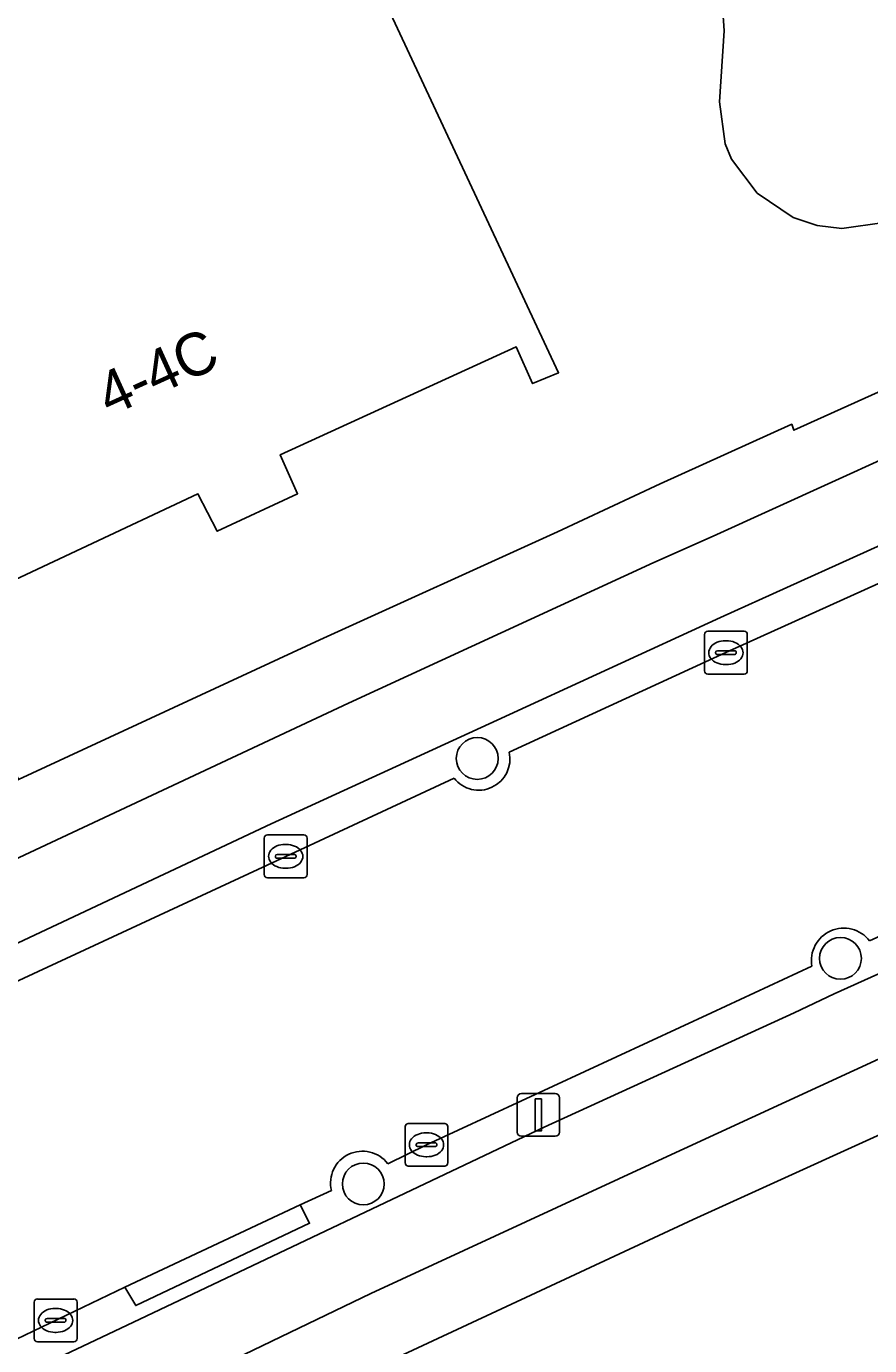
# Model space of a CAD drawing. Extents: x 157320 to 158835, y 386650 to 388491.
# Drawn here: x 157785.79 to 157805.51, y 387742.21 to 387773.08 of the extents above; entities that cross this region are included whole.
import ezdxf

# ---------------------------------------------------------------- set-up
doc = ezdxf.new("R2010")
doc.units = 0
for name, color, linetype in [('IMGEO_Berm_open', 7, 'Continuous'), ('IMGEO_Boom', 7, 'Continuous'), ('IMGEO_Erf', 7, 'Continuous'), ('IMGEO_Fietspad_open', 7, 'Continuous'), ('IMGEO_Kolk', 7, 'Continuous'), ('IMGEO_Lichtmast', 7, 'Continuous'), ('IMGEO_Pand', 7, 'Continuous'), ('IMGEO_Pand_nummerreeks', 7, 'Continuous'), ('IMGEO_Rijbaan_lokaal_open', 7, 'Continuous'), ('IMGEO_Voetpad_open', 7, 'Continuous')]:
    doc.layers.add(name, color=color, linetype=linetype)

msp = doc.modelspace()

# ---------------------------------------------------------------- linework, layer by layer
at = {"layer": 'IMGEO_Berm_open'}
for points in [[(157830.412, 387771.96), (157824.626, 387769.413), (157818.792, 387766.794), (157811.326, 387763.457), (157802.02, 387759.247), (157796.796, 387756.844), (157791.514, 387754.422), (157784.002, 387750.892), (157782.111, 387750), (157777.727, 387747.932), (157769.083, 387743.789), (157769.287, 387743.353), (157770.466, 387743.543), (157770.712, 387743.64), (157771.088, 387743.794)], [(157797.08, 387756.095), (157802.146, 387758.426), (157809.439, 387761.726)], [(157774.522, 387737.042), (157774.329, 387736.951), (157770.945, 387735.285), (157769.959, 387734.638), (157770.171, 387734.176), (157788.445, 387742.834), (157797.893, 387747.327), (157803.739, 387750), (157804.677, 387750.444), (157810.091, 387752.884), (157815.175, 387755.151), (157823.216, 387758.725)], [(157821.265, 387758.745), (157814.813, 387755.887), (157809.798, 387753.659), (157809.994, 387753.177), (157806.556, 387751.612), (157806.359, 387752.075), (157805.505, 387751.685)], [(157783.626, 387749.838), (157783.975, 387750), (157791.855, 387753.66), (157795.79, 387755.49)], [(157804.156, 387751.089), (157801.806, 387750), (157795.145, 387746.914), (157794.24, 387746.471)], [(157792.922, 387745.842), (157792.191, 387745.512), (157792.414, 387745.076), (157788.35, 387743.151), (157788.095, 387743.586), (157782.436, 387740.872), (157778.846, 387739.129)]]:
    msp.add_lwpolyline(points, dxfattribs=at)
msp.add_lwpolyline([(157792.414, 387745.076), (157792.191, 387745.512), (157788.095, 387743.586), (157788.35, 387743.151)], close=True, dxfattribs=at)
for centre, radius, start, end in [((157796.367, 387755.938), 0.73, 217.851, 12.4014), ((157804.903, 387751.223), 0.759, 37.5048, 190.1677), ((157793.648, 387746.016), 0.747, 37.5525, 193.472)]:
    msp.add_arc(centre, radius, start, end, dxfattribs=at)
at = {"layer": 'IMGEO_Boom'}
for centre in [(157796.332, 387755.951), (157804.824, 387751.274), (157793.668, 387745.996)]:
    msp.add_circle(centre, 0.489, dxfattribs=at)
at = {"layer": 'IMGEO_Erf'}
for points in [[(157805.842, 387768.492), (157804.852, 387768.352), (157804.279, 387768.423), (157803.719, 387768.609), (157802.878, 387769.172), (157802.279, 387769.973), (157802.125, 387770.327), (157801.998, 387771.315), (157802.102, 387772.972), (157802.021, 387774.247), (157801.408, 387776.7), (157801.444, 387777.329), (157801.556, 387777.747), (157801.982, 387778.5), (157802.775, 387779.152), (157803.626, 387777.358), (157804.993, 387778.006), (157802.456, 387783.356), (157816.749, 387790.135)], [(157773.659, 387781.323), (157777.46, 387772.709), (157791.548, 387779.289), (157798.235, 387764.975), (157797.627, 387764.722), (157797.242, 387765.581), (157791.728, 387763.055), (157792.131, 387762.142), (157790.254, 387761.268), (157789.801, 387762.139), (157784.354, 387759.587), (157784.75, 387758.69), (157784.186, 387758.429), (157785.609, 387755.46), (157792.651, 387758.723), (157798.206, 387761.256), (157800.606, 387762.378), (157803.685, 387763.769), (157803.737, 387763.63), (157814.47, 387768.474)], [(157864.126, 387772.947), (157837.386, 387761.239), (157831.138, 387758.491), (157825.817, 387756.137), (157813.3, 387750.568), (157812.042, 387750), (157807.394, 387747.901), (157801.377, 387745.165), (157794.254, 387741.847)]]:
    msp.add_lwpolyline(points, dxfattribs=at)
at = {"layer": 'IMGEO_Fietspad_open'}
for points in [[(157864.008, 387776.443), (157863.068, 387776.049), (157863.031, 387776.185), (157843.156, 387767.523), (157835.06, 387763.984), (157823.216, 387758.725), (157815.175, 387755.151), (157810.091, 387752.884), (157804.677, 387750.444), (157803.739, 387750), (157797.893, 387747.327), (157788.445, 387742.834), (157770.171, 387734.176), (157769.959, 387734.638)], [(157767.728, 387731.043), (157779.548, 387736.625), (157789.197, 387741.196), (157793.841, 387743.435), (157800.368, 387746.45), (157806.723, 387749.381), (157808.098, 387750), (157812.222, 387751.857), (157817.687, 387754.31), (157825.13, 387757.594), (157830.503, 387759.975), (157836.688, 387762.719), (157865.106, 387775.129)], [(157829.725, 387773.675), (157827.906, 387772.832), (157822.414, 387770.394), (157817.284, 387768.125), (157813.4, 387766.376), (157808.696, 387764.269), (157801.848, 387761.151), (157800.462, 387760.535), (157793.32, 387757.246), (157777.795, 387749.967), (157770.699, 387746.575), (157765.921, 387744.31)], [(157769.287, 387743.353), (157769.083, 387743.789), (157777.727, 387747.932), (157782.111, 387750), (157784.002, 387750.892), (157791.514, 387754.422), (157796.796, 387756.844), (157802.02, 387759.247), (157811.326, 387763.457), (157818.792, 387766.794), (157824.626, 387769.413), (157830.412, 387771.96)]]:
    msp.add_lwpolyline(points, dxfattribs=at)
at = {"layer": 'IMGEO_Kolk'}
for p, q in [((157801.645, 387758), (157801.645, 387758.852)), ((157801.72, 387758.926), (157802.572, 387758.926)), ((157802.646, 387758.852), (157802.646, 387758)), ((157802.133, 387758.706), (157802.158, 387758.706)), ((157801.904, 387758.42), (157801.904, 387758.432)), ((157802.342, 387758.383), (157801.944, 387758.383)), ((157801.947, 387758.469), (157802.345, 387758.469)), ((157802.388, 387758.432), (157802.388, 387758.42)), ((157802.572, 387757.926), (157801.72, 387757.926)), ((157802.156, 387758.146), (157802.131, 387758.146)), ((157791.428, 387754.161), (157792.28, 387754.161)), ((157791.353, 387753.235), (157791.353, 387754.087)), ((157791.841, 387753.941), (157791.866, 387753.941)), ((157792.354, 387754.087), (157792.354, 387753.235)), ((157791.612, 387753.655), (157791.612, 387753.667)), ((157792.05, 387753.618), (157791.652, 387753.618)), ((157791.655, 387753.704), (157792.053, 387753.704)), ((157792.096, 387753.667), (157792.096, 387753.655)), ((157791.864, 387753.381), (157791.839, 387753.381)), ((157792.28, 387753.161), (157791.428, 387753.161)), ((157794.72, 387747.413), (157795.572, 387747.413)), ((157794.645, 387746.487), (157794.645, 387747.339)), ((157795.133, 387747.193), (157795.158, 387747.193)), ((157795.646, 387747.339), (157795.646, 387746.487)), ((157794.904, 387746.907), (157794.904, 387746.919)), ((157795.342, 387746.87), (157794.944, 387746.87)), ((157794.947, 387746.956), (157795.345, 387746.956)), ((157795.388, 387746.919), (157795.388, 387746.907)), ((157795.156, 387746.633), (157795.131, 387746.633)), ((157795.572, 387746.413), (157794.72, 387746.413)), ((157785.974, 387742.379), (157785.974, 387743.231)), ((157786.049, 387743.305), (157786.901, 387743.305)), ((157786.462, 387743.085), (157786.487, 387743.085)), ((157786.975, 387743.231), (157786.975, 387742.379)), ((157786.233, 387742.799), (157786.233, 387742.811)), ((157786.671, 387742.762), (157786.273, 387742.762)), ((157786.276, 387742.848), (157786.674, 387742.848)), ((157786.717, 387742.811), (157786.717, 387742.799)), ((157786.485, 387742.525), (157786.46, 387742.525)), ((157786.901, 387742.305), (157786.049, 387742.305))]:
    msp.add_line(p, q, dxfattribs=at)
for points in [[(157801.645, 387758), (157801.645, 387758.852)], [(157801.72, 387758.926), (157802.572, 387758.926)], [(157802.646, 387758.852), (157802.646, 387758)], [(157802.572, 387757.926), (157801.72, 387757.926)], [(157791.428, 387754.161), (157792.28, 387754.161)], [(157791.353, 387753.235), (157791.353, 387754.087)], [(157792.354, 387754.087), (157792.354, 387753.235)], [(157792.28, 387753.161), (157791.428, 387753.161)], [(157794.72, 387747.413), (157795.572, 387747.413)], [(157794.645, 387746.487), (157794.645, 387747.339)], [(157795.646, 387747.339), (157795.646, 387746.487)], [(157795.572, 387746.413), (157794.72, 387746.413)], [(157785.974, 387742.379), (157785.974, 387743.231)], [(157786.049, 387743.305), (157786.901, 387743.305)], [(157786.975, 387743.231), (157786.975, 387742.379)], [(157786.901, 387742.305), (157786.049, 387742.305)]]:
    msp.add_lwpolyline(points, dxfattribs=at)
for centre, radius, start, end in [((157801.722, 387758.85), 0.0765, 91.552, 178.448), ((157801.722, 387758.85), 0.0765, 91.552, 178.448), ((157802.57, 387758.85), 0.0765, 1.552, 88.448), ((157802.57, 387758.85), 0.0765, 1.552, 88.448), ((157801.944, 387758.429), 0.0403, 85.8775, 175.7526), ((157801.941, 387758.419), 0.0366, 178.938, 274.7102), ((157802.345, 387758.426), 0.043, 264.8664, 352.4533), ((157802.349, 387758.431), 0.0386, 1.7309, 96.639), ((157801.722, 387758.002), 0.0765, 181.552, 268.448), ((157801.722, 387758.002), 0.0765, 181.552, 268.448), ((157802.57, 387758.002), 0.0765, 271.552, 358.448), ((157802.57, 387758.002), 0.0765, 271.552, 358.448), ((157791.43, 387754.085), 0.0765, 91.552, 178.448), ((157791.43, 387754.085), 0.0765, 91.552, 178.448), ((157792.278, 387754.085), 0.0765, 1.552, 88.448), ((157792.278, 387754.085), 0.0765, 1.552, 88.448), ((157791.652, 387753.664), 0.0403, 85.8775, 175.7526), ((157791.649, 387753.654), 0.0366, 178.938, 274.7102), ((157792.053, 387753.661), 0.043, 264.8664, 352.4533), ((157792.057, 387753.666), 0.0386, 1.7309, 96.639), ((157791.43, 387753.237), 0.0765, 181.552, 268.448), ((157791.43, 387753.237), 0.0765, 181.552, 268.448), ((157792.278, 387753.237), 0.0765, 271.552, 358.448), ((157792.278, 387753.237), 0.0765, 271.552, 358.448), ((157794.722, 387747.337), 0.0765, 91.552, 178.448), ((157794.722, 387747.337), 0.0765, 91.552, 178.448), ((157795.57, 387747.337), 0.0765, 1.552, 88.448), ((157795.57, 387747.337), 0.0765, 1.552, 88.448), ((157794.944, 387746.916), 0.0403, 85.8775, 175.7526), ((157794.941, 387746.906), 0.0366, 178.938, 274.7102), ((157795.345, 387746.913), 0.043, 264.8664, 352.4533), ((157795.349, 387746.918), 0.0386, 1.7309, 96.639), ((157794.722, 387746.489), 0.0765, 181.552, 268.448), ((157794.722, 387746.489), 0.0765, 181.552, 268.448), ((157795.57, 387746.489), 0.0765, 271.552, 358.448), ((157795.57, 387746.489), 0.0765, 271.552, 358.448), ((157786.051, 387743.229), 0.0765, 91.552, 178.448), ((157786.051, 387743.229), 0.0765, 91.552, 178.448), ((157786.899, 387743.229), 0.0765, 1.552, 88.448), ((157786.899, 387743.229), 0.0765, 1.552, 88.448), ((157786.273, 387742.808), 0.0403, 85.8775, 175.7526), ((157786.27, 387742.798), 0.0366, 178.938, 274.7102), ((157786.674, 387742.805), 0.043, 264.8664, 352.4533), ((157786.678, 387742.81), 0.0386, 1.7309, 96.639), ((157786.051, 387742.381), 0.0765, 181.552, 268.448), ((157786.051, 387742.381), 0.0765, 181.552, 268.448), ((157786.899, 387742.381), 0.0765, 271.552, 358.448), ((157786.899, 387742.381), 0.0765, 271.552, 358.448)]:
    msp.add_arc(centre, radius, start, end, dxfattribs=at)
for centre, major_axis, ratio, start_param, end_param in [((157802.132, 387758.426), (-0.387, 0.002), 0.722429, 4.712389, 7.853982), ((157802.157, 387758.426), (-0.39, 0.002), 0.717154, 1.570796, 4.712389), ((157791.84, 387753.661), (-0.387, 0.002), 0.722429, 4.712389, 7.853982), ((157791.865, 387753.661), (-0.39, 0.002), 0.717154, 1.570796, 4.712389), ((157795.132, 387746.913), (-0.387, 0.002), 0.722429, 4.712389, 7.853982), ((157795.157, 387746.913), (-0.39, 0.002), 0.717154, 1.570796, 4.712389), ((157786.461, 387742.805), (-0.387, 0.002), 0.722429, 4.712389, 7.853982), ((157786.486, 387742.805), (-0.39, 0.002), 0.717154, 1.570796, 4.712389)]:
    msp.add_ellipse(centre, major_axis=major_axis, ratio=ratio, start_param=start_param, end_param=end_param, dxfattribs=at)
at = {"layer": 'IMGEO_Lichtmast'}
for p, q in [((157797.264, 387747.211), (157797.264, 387748.011)), ((157797.264, 387748.011), (157797.264, 387747.211)), ((157797.364, 387748.111), (157798.154, 387748.111)), ((157798.154, 387748.111), (157797.364, 387748.111)), ((157798.254, 387748.011), (157798.254, 387747.211)), ((157798.254, 387747.211), (157798.254, 387748.011)), ((157798.154, 387747.111), (157797.364, 387747.111)), ((157797.364, 387747.111), (157798.154, 387747.111))]:
    msp.add_line(p, q, dxfattribs=at)
msp.add_lwpolyline([(157797.684, 387747.986), (157797.834, 387747.986), (157797.834, 387747.236), (157797.684, 387747.236), (157797.684, 387747.986)], dxfattribs=at)
for centre, start, end in [((157797.364, 387748.011), 90, 180), ((157797.364, 387748.011), 90, 180), ((157798.154, 387748.011), 0, 90), ((157798.154, 387748.011), 360, 90), ((157797.364, 387747.211), 180, 270), ((157797.364, 387747.211), 180, 270), ((157798.154, 387747.211), 270, 0), ((157798.154, 387747.211), 270, 0)]:
    msp.add_arc(centre, 0.1, start, end, dxfattribs=at)
at = {"layer": 'IMGEO_Pand'}
msp.add_lwpolyline([(157816.749, 387790.135), (157802.456, 387783.356), (157804.993, 387778.006), (157803.626, 387777.358), (157802.775, 387779.152), (157801.982, 387778.5), (157801.556, 387777.747), (157801.444, 387777.329), (157801.408, 387776.7), (157802.021, 387774.247), (157802.102, 387772.972), (157801.998, 387771.315), (157802.125, 387770.327), (157802.279, 387769.973), (157802.878, 387769.172), (157803.719, 387768.609), (157804.279, 387768.423), (157804.852, 387768.352), (157805.842, 387768.492)], dxfattribs=at)
msp.add_lwpolyline([(157792.131, 387762.142), (157791.728, 387763.055), (157797.242, 387765.581), (157797.627, 387764.722), (157798.235, 387764.975), (157791.548, 387779.289), (157777.46, 387772.709), (157783.032, 387760.878), (157784.186, 387758.429), (157784.75, 387758.69), (157784.354, 387759.587), (157789.801, 387762.139), (157790.254, 387761.268)], close=True, dxfattribs=at)
at = {"layer": 'IMGEO_Rijbaan_lokaal_open'}
for points in [[(157809.439, 387761.726), (157802.146, 387758.426), (157797.08, 387756.095)], [(157805.505, 387751.685), (157806.359, 387752.075), (157809.798, 387753.659), (157814.813, 387755.887), (157821.265, 387758.745)], [(157795.79, 387755.49), (157791.855, 387753.66), (157783.975, 387750), (157783.626, 387749.838)], [(157794.24, 387746.471), (157795.145, 387746.914), (157801.806, 387750), (157804.156, 387751.089)], [(157782.319, 387749.198), (157779.594, 387747.895), (157779.188, 387747.715), (157782.436, 387740.872), (157788.095, 387743.586), (157792.191, 387745.512), (157792.922, 387745.842)]]:
    msp.add_lwpolyline(points, dxfattribs=at)
for centre, radius, start, end in [((157796.367, 387755.938), 0.73, 217.851, 12.4014), ((157804.903, 387751.223), 0.759, 37.5048, 190.1677), ((157793.648, 387746.016), 0.747, 37.5525, 193.472)]:
    msp.add_arc(centre, radius, start, end, dxfattribs=at)
at = {"layer": 'IMGEO_Voetpad_open'}
for points in [[(157828.788, 387775.002), (157827.631, 387774.47), (157816.404, 387769.874), (157816.567, 387769.505), (157814.435, 387768.575), (157814.47, 387768.474), (157803.737, 387763.63), (157803.685, 387763.769), (157800.606, 387762.378), (157798.206, 387761.256), (157792.651, 387758.723), (157785.609, 387755.46), (157785.288, 387755.285), (157781.29, 387753.385), (157777.108, 387751.397), (157774.214, 387750), (157770.02, 387747.976), (157764.745, 387745.384)], [(157865.106, 387775.129), (157836.688, 387762.719), (157830.503, 387759.975), (157825.13, 387757.594), (157817.687, 387754.31), (157812.222, 387751.857), (157808.098, 387750), (157806.723, 387749.381), (157800.368, 387746.45), (157793.841, 387743.435), (157789.197, 387741.196), (157779.548, 387736.625), (157767.728, 387731.043)], [(157800.462, 387760.535), (157801.848, 387761.151), (157808.696, 387764.269), (157813.4, 387766.376), (157817.284, 387768.125), (157822.414, 387770.394), (157827.906, 387772.832), (157829.725, 387773.675)], [(157767.54, 387729.135), (157770.315, 387730.462), (157772.157, 387731.342), (157780.283, 387735.18), (157790.1, 387739.844), (157794.254, 387741.847), (157801.377, 387745.165), (157807.394, 387747.901), (157812.042, 387750), (157813.3, 387750.568), (157825.817, 387756.137), (157831.138, 387758.491), (157837.386, 387761.239), (157864.126, 387772.947)], [(157765.921, 387744.31), (157770.699, 387746.575), (157777.795, 387749.967), (157793.32, 387757.246), (157800.462, 387760.535)]]:
    msp.add_lwpolyline(points, dxfattribs=at)

# ---------------------------------------------------------------- texts
at = {"layer": 'IMGEO_Pand_nummerreeks'}
msp.add_text('4-4C', height=1, rotation=24.4288, dxfattribs=at).set_placement((157787.735, 387763.943))

doc.saveas('drawing.dxf')
